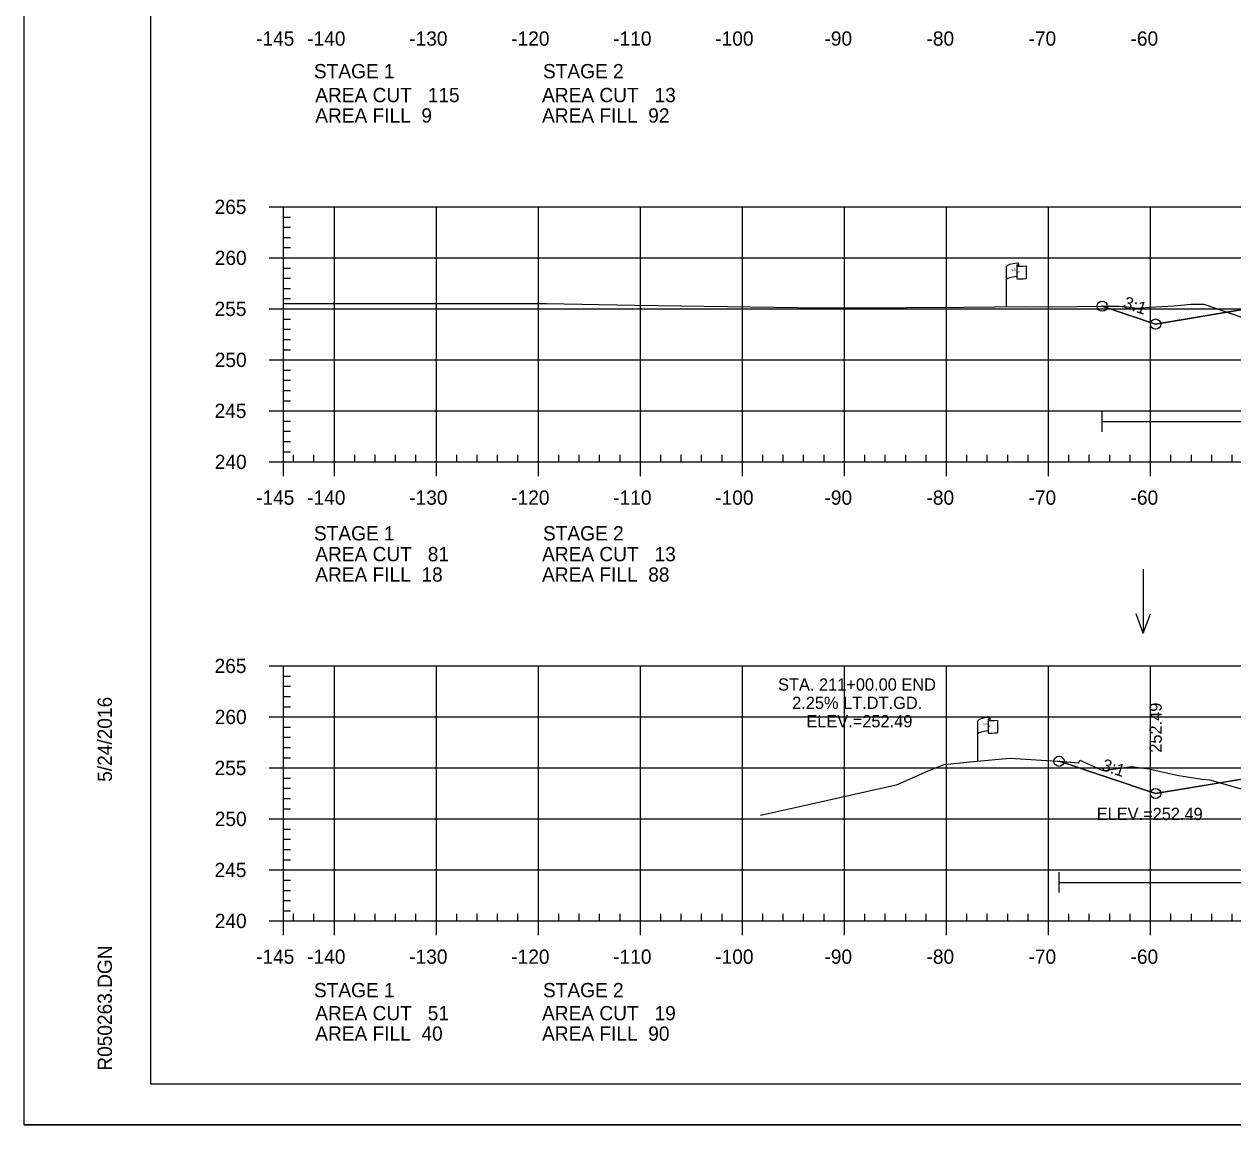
# Model space of a CAD drawing. Extents: x 1365647 to 1367999, y 387113 to 400173.
# Drawn here: x 1365723.7 to 1365842.2, y 390572.8 to 390680.7 of the extents above; entities that cross this region are included whole.
import ezdxf

# ---------------------------------------------------------------- set-up
doc = ezdxf.new("R2010")
doc.units = 0
for name, color, linetype in [('E_Existing ROW', 7, 'Continuous'), ('R_Axis', 7, 'Continuous'), ('R_Axis Annot', 7, 'Continuous'), ('R_Border', 7, 'Continuous'), ('R_Border Notes', 7, 'Continuous'), ('R_Contours', 7, 'Continuous'), ('R_Exist Surface', 7, 'Continuous'), ('R_Fin Surface', 7, 'Continuous'), ('R_Fin Surface Annot', 7, 'Continuous'), ('R_Grid', 7, 'Continuous'), ('R_No Plot', 7, 'Continuous'), ('R_Proposed Const Limits', 7, 'Continuous'), ('R_Water', 7, 'Continuous'), ('R_Water Annot', 7, 'Continuous')]:
    doc.layers.add(name, color=color, linetype=linetype)

msp = doc.modelspace()

# ---------------------------------------------------------------- linework, layer by layer
at = {"layer": 'E_Existing ROW'}
for p, q in [((1365819.98, 390653), (1365819.98, 390656.95)), ((1365820.98, 390657.05), (1365820.98, 390657.03)), ((1365820.98, 390657.03), (1365820.98, 390655.81)), ((1365821.14, 390657.2), (1365821.14, 390656.96)), ((1365821.91, 390657.01), (1365821.91, 390655.77)), ((1365817.17, 390608.47), (1365817.17, 390612.42)), ((1365818.17, 390612.51), (1365818.17, 390612.5)), ((1365818.17, 390612.5), (1365818.17, 390611.27)), ((1365818.33, 390612.67), (1365818.33, 390612.43)), ((1365819.1, 390612.47), (1365819.1, 390611.23))]:
    msp.add_line(p, q, dxfattribs=at)
for centre, radius, start, end in [((1365821.06, 390657.05), 0.078, 88.6458, 274.2828), ((1365821.07, 390657.2), 0.0783, 263.0712, 93.9564), ((1365821.06, 390655.81), 0.0783, 180, 273.9564), ((1365818.24, 390612.51), 0.078, 88.6458, 274.2828), ((1365818.26, 390612.67), 0.0783, 263.0712, 93.9564), ((1365818.25, 390611.27), 0.0783, 180, 273.9564)]:
    msp.add_arc(centre, radius, start, end, dxfattribs=at)
for centre, major_axis, ratio, start_param, end_param in [((1365821.56, 390656.99), (-1.58, -0.04), 0.19887, 5.030368, 6.283185), ((1365822.27, 390657.11), (-1.23, -0.13), 0.052933, 0.159456, 1.268315), ((1365821.56, 390655.68), (-1.58, -0.04), 0.19887, 5.083035, 6.194897), ((1365822.27, 390655.87), (-1.23, -0.13), 0.052933, 0.159456, 1.268315), ((1365818.75, 390612.46), (-1.58, -0.04), 0.19887, 5.030368, 6.283185), ((1365819.46, 390612.58), (-1.23, -0.13), 0.052933, 0.159456, 1.268315), ((1365818.75, 390611.14), (-1.58, -0.04), 0.19887, 5.083035, 6.194897), ((1365819.46, 390611.34), (-1.23, -0.13), 0.052933, 0.159456, 1.268315)]:
    msp.add_ellipse(centre, major_axis=major_axis, ratio=ratio, start_param=start_param, end_param=end_param, dxfattribs=at)
at = {"layer": 'R_Axis'}
for p, q in [((1365747.69, 390662.79), (1365749.09, 390662.79)), ((1365749.09, 390637.79), (1365749.09, 390662.79)), ((1365749.09, 390661.79), (1365749.79, 390661.79)), ((1365749.09, 390660.79), (1365749.79, 390660.79)), ((1365749.09, 390659.79), (1365749.79, 390659.79)), ((1365749.09, 390658.79), (1365749.79, 390658.79)), ((1365747.69, 390657.79), (1365749.09, 390657.79)), ((1365749.09, 390656.79), (1365749.79, 390656.79)), ((1365749.09, 390655.79), (1365749.79, 390655.79)), ((1365749.09, 390654.79), (1365749.79, 390654.79)), ((1365749.09, 390653.79), (1365749.79, 390653.79)), ((1365747.69, 390652.79), (1365749.09, 390652.79)), ((1365749.09, 390651.79), (1365749.79, 390651.79)), ((1365749.09, 390650.79), (1365749.79, 390650.79)), ((1365749.09, 390649.79), (1365749.79, 390649.79)), ((1365749.09, 390648.79), (1365749.79, 390648.79)), ((1365747.69, 390647.79), (1365749.09, 390647.79)), ((1365749.09, 390646.79), (1365749.79, 390646.79)), ((1365749.09, 390645.79), (1365749.79, 390645.79)), ((1365749.09, 390644.79), (1365749.79, 390644.79)), ((1365749.09, 390643.79), (1365749.79, 390643.79)), ((1365747.69, 390642.79), (1365749.09, 390642.79)), ((1365749.09, 390641.79), (1365749.79, 390641.79)), ((1365749.09, 390640.79), (1365749.79, 390640.79)), ((1365749.09, 390639.79), (1365749.79, 390639.79)), ((1365747.69, 390637.79), (1365749.09, 390637.79)), ((1365749.09, 390638.79), (1365749.79, 390638.79)), ((1365749.09, 390637.79), (1365749.09, 390638.49)), ((1365749.09, 390637.79), (1366039.09, 390637.79)), ((1365749.09, 390636.39), (1365749.09, 390637.79)), ((1365750.09, 390637.79), (1365750.09, 390638.49)), ((1365752.09, 390637.79), (1365752.09, 390638.49)), ((1365754.09, 390636.39), (1365754.09, 390637.79)), ((1365756.09, 390637.79), (1365756.09, 390638.49)), ((1365758.09, 390637.79), (1365758.09, 390638.49)), ((1365760.09, 390637.79), (1365760.09, 390638.49)), ((1365762.09, 390637.79), (1365762.09, 390638.49)), ((1365764.09, 390636.39), (1365764.09, 390637.79)), ((1365766.09, 390637.79), (1365766.09, 390638.49)), ((1365768.09, 390637.79), (1365768.09, 390638.49)), ((1365770.09, 390637.79), (1365770.09, 390638.49)), ((1365772.09, 390637.79), (1365772.09, 390638.49)), ((1365774.09, 390636.39), (1365774.09, 390637.79)), ((1365776.09, 390637.79), (1365776.09, 390638.49)), ((1365778.09, 390637.79), (1365778.09, 390638.49)), ((1365780.09, 390637.79), (1365780.09, 390638.49)), ((1365782.09, 390637.79), (1365782.09, 390638.49)), ((1365784.09, 390636.39), (1365784.09, 390637.79)), ((1365786.09, 390637.79), (1365786.09, 390638.49)), ((1365788.09, 390637.79), (1365788.09, 390638.49)), ((1365790.09, 390637.79), (1365790.09, 390638.49)), ((1365792.09, 390637.79), (1365792.09, 390638.49)), ((1365794.09, 390636.39), (1365794.09, 390637.79)), ((1365796.09, 390637.79), (1365796.09, 390638.49)), ((1365798.09, 390637.79), (1365798.09, 390638.49)), ((1365800.09, 390637.79), (1365800.09, 390638.49)), ((1365802.09, 390637.79), (1365802.09, 390638.49)), ((1365804.09, 390636.39), (1365804.09, 390637.79)), ((1365806.09, 390637.79), (1365806.09, 390638.49)), ((1365808.09, 390637.79), (1365808.09, 390638.49)), ((1365810.09, 390637.79), (1365810.09, 390638.49)), ((1365812.09, 390637.79), (1365812.09, 390638.49)), ((1365814.09, 390636.39), (1365814.09, 390637.79)), ((1365816.09, 390637.79), (1365816.09, 390638.49)), ((1365818.09, 390637.79), (1365818.09, 390638.49)), ((1365820.09, 390637.79), (1365820.09, 390638.49)), ((1365822.09, 390637.79), (1365822.09, 390638.49)), ((1365824.09, 390636.39), (1365824.09, 390637.79)), ((1365826.09, 390637.79), (1365826.09, 390638.49)), ((1365828.09, 390637.79), (1365828.09, 390638.49)), ((1365830.09, 390637.79), (1365830.09, 390638.49)), ((1365832.09, 390637.79), (1365832.09, 390638.49)), ((1365834.09, 390636.39), (1365834.09, 390637.79)), ((1365836.09, 390637.79), (1365836.09, 390638.49)), ((1365838.09, 390637.79), (1365838.09, 390638.49)), ((1365840.09, 390637.79), (1365840.09, 390638.49)), ((1365842.09, 390637.79), (1365842.09, 390638.49)), ((1365747.69, 390617.79), (1365749.09, 390617.79)), ((1365749.09, 390592.79), (1365749.09, 390617.79)), ((1365749.09, 390616.79), (1365749.79, 390616.79)), ((1365749.09, 390615.79), (1365749.79, 390615.79)), ((1365749.09, 390614.79), (1365749.79, 390614.79)), ((1365749.09, 390613.79), (1365749.79, 390613.79)), ((1365747.69, 390612.79), (1365749.09, 390612.79)), ((1365749.09, 390611.79), (1365749.79, 390611.79)), ((1365749.09, 390610.79), (1365749.79, 390610.79)), ((1365749.09, 390609.79), (1365749.79, 390609.79)), ((1365749.09, 390608.79), (1365749.79, 390608.79)), ((1365747.69, 390607.79), (1365749.09, 390607.79)), ((1365749.09, 390606.79), (1365749.79, 390606.79)), ((1365749.09, 390605.79), (1365749.79, 390605.79)), ((1365749.09, 390604.79), (1365749.79, 390604.79)), ((1365749.09, 390603.79), (1365749.79, 390603.79)), ((1365747.69, 390602.79), (1365749.09, 390602.79)), ((1365749.09, 390601.79), (1365749.79, 390601.79)), ((1365749.09, 390600.79), (1365749.79, 390600.79)), ((1365749.09, 390599.79), (1365749.79, 390599.79)), ((1365749.09, 390598.79), (1365749.79, 390598.79)), ((1365747.69, 390597.79), (1365749.09, 390597.79)), ((1365749.09, 390596.79), (1365749.79, 390596.79)), ((1365749.09, 390595.79), (1365749.79, 390595.79)), ((1365749.09, 390594.79), (1365749.79, 390594.79)), ((1365747.69, 390592.79), (1365749.09, 390592.79)), ((1365749.09, 390593.79), (1365749.79, 390593.79)), ((1365749.09, 390592.79), (1365749.09, 390593.49)), ((1365749.09, 390592.79), (1366039.09, 390592.79)), ((1365749.09, 390591.39), (1365749.09, 390592.79)), ((1365750.09, 390592.79), (1365750.09, 390593.49)), ((1365752.09, 390592.79), (1365752.09, 390593.49)), ((1365754.09, 390591.39), (1365754.09, 390592.79)), ((1365756.09, 390592.79), (1365756.09, 390593.49)), ((1365758.09, 390592.79), (1365758.09, 390593.49)), ((1365760.09, 390592.79), (1365760.09, 390593.49)), ((1365762.09, 390592.79), (1365762.09, 390593.49)), ((1365764.09, 390591.39), (1365764.09, 390592.79)), ((1365766.09, 390592.79), (1365766.09, 390593.49)), ((1365768.09, 390592.79), (1365768.09, 390593.49)), ((1365770.09, 390592.79), (1365770.09, 390593.49)), ((1365772.09, 390592.79), (1365772.09, 390593.49)), ((1365774.09, 390591.39), (1365774.09, 390592.79)), ((1365776.09, 390592.79), (1365776.09, 390593.49)), ((1365778.09, 390592.79), (1365778.09, 390593.49)), ((1365780.09, 390592.79), (1365780.09, 390593.49)), ((1365782.09, 390592.79), (1365782.09, 390593.49)), ((1365784.09, 390591.39), (1365784.09, 390592.79)), ((1365786.09, 390592.79), (1365786.09, 390593.49)), ((1365788.09, 390592.79), (1365788.09, 390593.49)), ((1365790.09, 390592.79), (1365790.09, 390593.49)), ((1365792.09, 390592.79), (1365792.09, 390593.49)), ((1365794.09, 390591.39), (1365794.09, 390592.79)), ((1365796.09, 390592.79), (1365796.09, 390593.49)), ((1365798.09, 390592.79), (1365798.09, 390593.49)), ((1365800.09, 390592.79), (1365800.09, 390593.49)), ((1365802.09, 390592.79), (1365802.09, 390593.49)), ((1365804.09, 390591.39), (1365804.09, 390592.79)), ((1365806.09, 390592.79), (1365806.09, 390593.49)), ((1365808.09, 390592.79), (1365808.09, 390593.49)), ((1365810.09, 390592.79), (1365810.09, 390593.49)), ((1365812.09, 390592.79), (1365812.09, 390593.49)), ((1365814.09, 390591.39), (1365814.09, 390592.79)), ((1365816.09, 390592.79), (1365816.09, 390593.49)), ((1365818.09, 390592.79), (1365818.09, 390593.49)), ((1365820.09, 390592.79), (1365820.09, 390593.49)), ((1365822.09, 390592.79), (1365822.09, 390593.49)), ((1365824.09, 390591.39), (1365824.09, 390592.79)), ((1365826.09, 390592.79), (1365826.09, 390593.49)), ((1365828.09, 390592.79), (1365828.09, 390593.49)), ((1365830.09, 390592.79), (1365830.09, 390593.49)), ((1365832.09, 390592.79), (1365832.09, 390593.49)), ((1365834.09, 390591.39), (1365834.09, 390592.79)), ((1365836.09, 390592.79), (1365836.09, 390593.49)), ((1365838.09, 390592.79), (1365838.09, 390593.49)), ((1365840.09, 390592.79), (1365840.09, 390593.49)), ((1365842.09, 390592.79), (1365842.09, 390593.49))]:
    msp.add_line(p, q, dxfattribs=at)
at = {"layer": 'R_Border'}
for p, q in [((1365736.09, 390576.79), (1365736.09, 390782.25)), ((1365736.09, 390576.79), (1365736.09, 390576.79)), ((1366052.27, 390576.79), (1365736.09, 390576.79))]:
    msp.add_line(p, q, dxfattribs=at)
at = {"layer": 'R_Contours'}
for points in [[(1365829.35, 390653.05), (1365830.97, 390653.06), (1365831.31, 390653.03), (1365831.52, 390653.01), (1365832.79, 390652.86), (1365833.99, 390652.97), (1365836.41, 390653.09), (1365838.08, 390653.24), (1365839.33, 390653.24), (1365841.58, 390652.46), (1365834.59, 390651.3)], [(1365841.58, 390652.46), (1365843.9, 390651.67), (1365846.86, 390650.64), (1365848.16, 390650.34), (1365848.95, 390650.2), (1365853.73, 390649.78), (1365858.75, 390649.4), (1365859.1, 390649.47), (1365860.63, 390649.55), (1365863.37, 390649.77), (1365865.96, 390649.78), (1365867.46, 390649.8), (1365869.92, 390650.64), (1365870.56, 390650.86), (1365870.9, 390650.98), (1365874.12, 390652.15), (1365875.12, 390652.26), (1365876.66, 390652.38), (1365878.56, 390652.5), (1365862.59, 390653.23), (1365843.94, 390652.86)], [(1365825.12, 390608.44), (1365827.05, 390608.29), (1365827.17, 390608.54), (1365829.19, 390607.62), (1365829.58, 390607.51), (1365829.98, 390607.61), (1365832.22, 390607.94), (1365833.92, 390607.69), (1365836.67, 390607.07), (1365839.12, 390606.7), (1365839.88, 390606.61), (1365840.91, 390606.33), (1365834.59, 390605.28)], [(1365840.91, 390606.33), (1365841.94, 390606.05), (1365847.99, 390604.3), (1365849.96, 390603.96), (1365850.25, 390603.87), (1365853.99, 390603.58), (1365857.19, 390603.3), (1365857.98, 390603.3), (1365859.6, 390603.33), (1365863.02, 390603.36), (1365863.35, 390603.46), (1365864.25, 390603.64), (1365864.55, 390603.7), (1365866.51, 390604.05), (1365869.86, 390605.27), (1365870.16, 390605.36), (1365870.51, 390605.45), (1365874.26, 390606.45), (1365875.19, 390606.72), (1365876.21, 390606.89), (1365862.59, 390607.3), (1365844.58, 390606.94)]]:
    msp.add_lwpolyline(points, close=True, dxfattribs=at)
at = {"layer": 'R_Exist Surface'}
for points in [[(1365749.09, 390653.3), (1365768.26, 390653.31), (1365774.88, 390653.31), (1365783.5, 390653.16), (1365799.46, 390652.93), (1365804.55, 390652.9), (1365815.8, 390652.95), (1365821.86, 390653.02), (1365824.48, 390652.99), (1365829.22, 390653.05), (1365830.97, 390653.06), (1365831.31, 390653.03), (1365831.52, 390653.01), (1365832.79, 390652.86), (1365833.99, 390652.97), (1365836.41, 390653.09), (1365838.08, 390653.24), (1365839.33, 390653.24), (1365843.9, 390651.67)], [(1365795.85, 390603.15), (1365799.55, 390603.97), (1365809.3, 390606.17), (1365812.29, 390607.49), (1365813.86, 390608.11), (1365816.74, 390608.43), (1365820.31, 390608.76), (1365824.98, 390608.45), (1365827.05, 390608.29), (1365827.17, 390608.54), (1365829.19, 390607.62), (1365829.58, 390607.51), (1365829.98, 390607.61), (1365832.22, 390607.94), (1365833.92, 390607.69), (1365836.67, 390607.07), (1365839.12, 390606.7), (1365839.88, 390606.61), (1365841.94, 390606.05), (1365847.99, 390604.3)]]:
    msp.add_lwpolyline(points, dxfattribs=at)
at = {"layer": 'R_Fin Surface'}
for points in [[(1365829.35, 390653.05), (1365834.59, 390651.3), (1365843.94, 390652.86), (1365856.59, 390654.97), (1365862.59, 390654.69), (1365864.59, 390654.6), (1365894.09, 390653.24), (1365923.59, 390651.89), (1365925.59, 390651.79), (1365931.59, 390651.52), (1365943.69, 390649.5), (1365953.59, 390647.85), (1365957.07, 390646.69), (1365970.89, 390651.3)], [(1365825.12, 390608.44), (1365834.59, 390605.28), (1365834.59, 390605.28), (1365844.58, 390606.94), (1365856.59, 390608.94), (1365862.59, 390608.76), (1365864.59, 390608.7), (1365894.09, 390607.8), (1365923.59, 390606.91), (1365925.59, 390606.84), (1365931.59, 390606.6), (1365941.88, 390604.89), (1365953.59, 390602.94), (1365958.47, 390601.31), (1365969.18, 390604.88)]]:
    msp.add_lwpolyline(points, dxfattribs=at)
at = {"layer": 'R_Grid'}
for p, q in [((1365749.09, 390662.79), (1366039.09, 390662.79)), ((1365749.09, 390637.79), (1365749.09, 390662.79)), ((1365754.09, 390637.79), (1365754.09, 390662.79)), ((1365764.09, 390637.79), (1365764.09, 390662.79)), ((1365774.09, 390637.79), (1365774.09, 390662.79)), ((1365784.09, 390637.79), (1365784.09, 390662.79)), ((1365794.09, 390637.79), (1365794.09, 390662.79)), ((1365804.09, 390637.79), (1365804.09, 390662.79)), ((1365814.09, 390637.79), (1365814.09, 390662.79)), ((1365824.09, 390637.79), (1365824.09, 390662.79)), ((1365834.09, 390637.79), (1365834.09, 390662.79)), ((1365749.09, 390657.79), (1366039.09, 390657.79)), ((1365749.09, 390652.79), (1366039.09, 390652.79)), ((1365749.09, 390647.79), (1366039.09, 390647.79)), ((1365749.09, 390642.79), (1366039.09, 390642.79)), ((1365749.09, 390637.79), (1366039.09, 390637.79)), ((1365749.09, 390617.79), (1366039.09, 390617.79)), ((1365749.09, 390592.79), (1365749.09, 390617.79)), ((1365754.09, 390592.79), (1365754.09, 390617.79)), ((1365764.09, 390592.79), (1365764.09, 390617.79)), ((1365774.09, 390592.79), (1365774.09, 390617.79)), ((1365784.09, 390592.79), (1365784.09, 390617.79)), ((1365794.09, 390592.79), (1365794.09, 390617.79)), ((1365804.09, 390592.79), (1365804.09, 390617.79)), ((1365814.09, 390592.79), (1365814.09, 390617.79)), ((1365824.09, 390592.79), (1365824.09, 390617.79)), ((1365834.09, 390592.79), (1365834.09, 390617.79)), ((1365749.09, 390612.79), (1366039.09, 390612.79)), ((1365749.09, 390607.79), (1366039.09, 390607.79)), ((1365749.09, 390602.79), (1366039.09, 390602.79)), ((1365749.09, 390597.79), (1366039.09, 390597.79)), ((1365749.09, 390592.79), (1366039.09, 390592.79))]:
    msp.add_line(p, q, dxfattribs=at)
at = {"layer": 'R_No Plot'}
msp.add_line((1365723.69, 390572.81), (1366057.03, 390572.81), dxfattribs=at)
msp.add_lwpolyline([(1365723.69, 390786.14), (1366057.03, 390786.14), (1366057.03, 390572.8), (1365723.69, 390572.8)], close=True, dxfattribs=at)
for centre in [(1365829.35, 390653.05), (1365829.35, 390653.05), (1365834.59, 390651.3), (1365834.59, 390651.3), (1365834.59, 390651.3), (1365834.59, 390651.3), (1365834.59, 390651.3), (1365825.12, 390608.44), (1365825.12, 390608.44), (1365834.59, 390605.28), (1365834.59, 390605.28), (1365834.59, 390605.28), (1365834.59, 390605.28), (1365834.59, 390605.28), (1365834.59, 390605.28), (1365834.59, 390605.28)]:
    msp.add_circle(centre, 0.5, dxfattribs=at)
at = {"layer": 'R_Proposed Const Limits'}
for points in [[(1365856.59, 390654.97), (1365834.59, 390651.3), (1365829.35, 390653.05)], [(1365834.59, 390605.28), (1365825.12, 390608.44)]]:
    msp.add_lwpolyline(points, dxfattribs=at)
at = {"layer": 'R_Water'}
for p, q in [((1365829.35, 390640.75), (1365829.35, 390642.75)), ((1365829.35, 390641.75), (1365881.99, 390641.75)), ((1365825.12, 390595.57), (1365825.12, 390597.57)), ((1365825.12, 390596.57), (1365881.98, 390596.57))]:
    msp.add_line(p, q, dxfattribs=at)
at = {"layer": 'R_Water Annot'}
for p, q in [((1365833.38, 390627.27), (1365833.38, 390620.99)), ((1365833.38, 390620.99), (1365832.68, 390622.91)), ((1365833.38, 390620.99), (1365834.08, 390622.91))]:
    msp.add_line(p, q, dxfattribs=at)

# ---------------------------------------------------------------- texts
at = {"layer": 'E_Existing ROW'}
for s, height, rotation, p in [('R ', 0.2, 9.9884, (1365820.5, 390656.45)), (' O', 0.2, 9.9884, (1365820.65, 390656.5)), ('DWB 11-9-07', 0.001, 90, (1365821.14, 390656.96)), ('W', 0.2, 351.1788, (1365820.98, 390656.33)), ('DWB 11-9-07', 0.001, 5.0717, (1365821.9, 390655.77)), ('DWB 11-9-07', 0.001, 90, (1365819.98, 390653)), ('R ', 0.2, 9.9884, (1365817.69, 390611.92)), (' O', 0.2, 9.9884, (1365817.84, 390611.96)), ('W', 0.2, 351.1788, (1365818.17, 390611.79)), ('DWB 11-9-07', 0.001, 90, (1365818.33, 390612.43)), ('DWB 11-9-07', 0.001, 5.0717, (1365819.09, 390611.23)), ('DWB 11-9-07', 0.001, 90, (1365817.17, 390608.47))]:
    msp.add_text(s, height=height, rotation=rotation, dxfattribs=at).set_placement(p)
at = {"layer": 'R_Axis Annot'}
for s, p in [('-145', (1365746.42, 390678.59)), ('-140', (1365751.43, 390678.59)), ('-130', (1365761.43, 390678.59)), ('-120', (1365771.43, 390678.59)), ('-110', (1365781.43, 390678.59)), ('-100', (1365791.43, 390678.59)), ('-90', (1365802.13, 390678.59)), ('-80', (1365812.13, 390678.59)), ('-70', (1365822.13, 390678.59)), ('-60', (1365832.13, 390678.59)), ('STAGE 1', (1365752.09, 390675.39)), ('STAGE 2', (1365774.54, 390675.39)), ('AREA CUT   115', (1365752.22, 390673.05)), ('AREA CUT   13', (1365774.45, 390673.05)), ('AREA FILL  9', (1365752.22, 390671.05)), ('AREA FILL  92', (1365774.45, 390671.05)), ('265', (1365742.35, 390662.09)), ('260', (1365742.37, 390657.09)), ('255', (1365742.35, 390652.09)), ('250', (1365742.37, 390647.09)), ('245', (1365742.35, 390642.09)), ('240', (1365742.37, 390637.09)), ('-145', (1365746.42, 390633.59)), ('-140', (1365751.43, 390633.59)), ('-130', (1365761.43, 390633.59)), ('-120', (1365771.43, 390633.59)), ('-110', (1365781.43, 390633.59)), ('-100', (1365791.43, 390633.59)), ('-90', (1365802.13, 390633.59)), ('-80', (1365812.13, 390633.59)), ('-70', (1365822.13, 390633.59)), ('-60', (1365832.13, 390633.59)), ('STAGE 1', (1365752.09, 390630.09)), ('STAGE 2', (1365774.54, 390630.09)), ('AREA CUT   81', (1365752.22, 390628.05)), ('AREA CUT   13', (1365774.45, 390628.05)), ('AREA FILL  18', (1365752.22, 390626.05)), ('AREA FILL  88', (1365774.45, 390626.05)), ('265', (1365742.35, 390617.09)), ('260', (1365742.37, 390612.09)), ('255', (1365742.35, 390607.09)), ('250', (1365742.37, 390602.09)), ('245', (1365742.35, 390597.09)), ('240', (1365742.37, 390592.09)), ('-145', (1365746.42, 390588.59)), ('-140', (1365751.43, 390588.59)), ('-130', (1365761.43, 390588.59)), ('-120', (1365771.43, 390588.59)), ('-110', (1365781.43, 390588.59)), ('-100', (1365791.43, 390588.59)), ('-90', (1365802.13, 390588.59)), ('-80', (1365812.13, 390588.59)), ('-70', (1365822.13, 390588.59)), ('-60', (1365832.13, 390588.59)), ('STAGE 1', (1365752.09, 390585.31)), ('STAGE 2', (1365774.54, 390585.31)), ('AREA CUT   51', (1365752.22, 390583.05)), ('AREA CUT   19', (1365774.45, 390583.05)), ('AREA FILL  40', (1365752.22, 390581.05)), ('AREA FILL  90', (1365774.45, 390581.05))]:
    msp.add_text(s, height=1.4, dxfattribs=at).set_placement(p)
at = {"layer": 'R_Border'}
for s, p in [('5/24/2016', (1365732.29, 390606.43)), ('R050263.DGN', (1365732.29, 390578.11))]:
    msp.add_text(s, height=1.4, rotation=90, dxfattribs=at).set_placement(p)
at = {"layer": 'R_Border Notes'}
msp.add_text('ELEV.=252.49', height=1.2, dxfattribs=at).set_placement((1365828.81, 390602.68))
at = {"layer": 'R_Fin Surface Annot'}
for s, rotation, p in [('3:1', 341.5651, (1365831.34, 390652.91)), ('252.49', 90, (1365835.19, 390609.28)), ('3:1', 341.5651, (1365829.22, 390607.59))]:
    msp.add_text(s, height=1.2, rotation=rotation, dxfattribs=at).set_placement(p)
at = {"layer": 'R_Water'}
for s, p in [('STA. 211+00.00 END', (1365797.58, 390615.37)), ('2.25% LT.DT.GD.', (1365798.96, 390613.57)), ('ELEV.=252.49', (1365800.35, 390611.77))]:
    msp.add_text(s, height=1.2, dxfattribs=at).set_placement(p)

doc.saveas('drawing.dxf')
